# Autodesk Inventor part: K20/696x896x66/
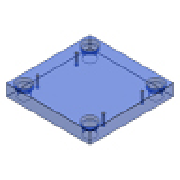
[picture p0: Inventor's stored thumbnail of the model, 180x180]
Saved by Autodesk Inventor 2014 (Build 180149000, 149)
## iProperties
IsCustomPart: 1
Created: 2009-11
Part Number: K20/696x896x66/
Material: DIN 1.1730
Description: Cavity Plate
Document SubType Name: Modeling
Designer: gaom
Standard Revision: 1
Manufacturer: HASCO
Language: en-US
Size Designation: 696x896x66/
Categories: <MemberInstance><Categories><Category DisplayName="Mold" InternalName="349578f2-f4d4-4954-8c09-8e99297a61c0" Mnemonic="MOLD"><Category DisplayName="Mold Plates"
Density: 7.82 g/cm^3
Appearance: Clear - Blue
Author: gaom
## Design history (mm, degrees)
sketch "Sketch1"
  geometry: L1 (-348, 448)-(348, 448); L2 (348, 448)-(348, -448); L3 (348, -448)-(-348, -448); L4 (-348, -448)-(-348, 448); 3 further points
  constraints: 8 end point, 2 midpoint, 2 parallel, 1 horizontal, 1 horizontal alignment, 1 perpendicular, 1 vertical alignment
  dimensions: "d126" = 696 distance between parallel lines of L2 L4 (= TW_); "d127" = 896 distance between parallel lines of L3 L1 (= TL)
extrude "Extrusion1" new body sketch "Sketch1" distance "d20" = 66 (= H_); taper "d30" = 0 deg
sketch "Sketch2"
  geometry: 6 further points
  dimensions: "d128" = 296 horizontal distance of point (0, 0) point (-296, 337) (= 0.5 x S1_W); "d129" = 337 vertical distance of point (0, 0) point (-296, 337) (= 0.5 x S1_L); "d130" = 396 vertical distance of point (0, 0) point (-296, 396) (= 0.5 x GP_L); "d131" = 296 horizontal distance of point (0, 0) point (-296, 396) (= 0.5 x GP_W); "d161" = 296 horizontal distance of point (0, 0) point (-296, -396) (= 0.5 x GP_W); "d162" = 396 vertical distance of point (0, 0) point (-296, -396) (= 0.5 x GP_L); "d163" = 296 horizontal distance of point (0, 0) point (296, 396) (= 0.5 x GP_W); "d164" = 396 vertical distance of point (0, 0) point (296, 396) (= 0.5 x GP_L); "d165" = 296 horizontal distance of point (296, -396) point (0, 0) (= 0.5 x GP_W); "d166" = 396 vertical distance of point (0, 0) point (296, -396) (= 0.5 x GP_L)
feature "Sculpt6"
sketch "Sketch3"
  geometry: 4 further points
hole "Hole14" sketch "Sketch3" at (142, 279.032), (-78, 279.032), (78, -279.032), (-142, -279.032) diameter "d188" = 3.4; stored, may be unused: countersink angle "d192" = 90 deg, drill point angle "d194" = 0 deg; dims "d189" = 6, "d190" = 4, "d191" = 2, "d193" = 8
sketch "Sketch4"
  geometry: 4 further points
hole "Hole15" sketch "Sketch4" at (154, 180.032), (-66, 180.032), (66, -180.032), (-154, -180.032) diameter "d195" = 3.4; stored, may be unused: countersink angle "d199" = 90 deg, drill point angle "d201" = 0 deg; dims "d196" = 6, "d197" = 4, "d198" = 2, "d200" = 8
sketch "Sketch5"
  geometry: 4 further points
hole "Hole16" sketch "Sketch5" at (78, 279.032), (-142, 279.032), (142, -279.032), (-78, -279.032) diameter "d202" = 3.4; stored, may be unused: countersink angle "d206" = 90 deg, drill point angle "d208" = 0 deg; dims "d203" = 6, "d204" = 4, "d205" = 2, "d207" = 8
sketch "Sketch6"
  geometry: 4 further points
hole "Hole17" sketch "Sketch6" at (66, 180.032), (-154, 180.032), (154, -180.032), (-66, -180.032) diameter "d209" = 3.4; stored, may be unused: countersink angle "d213" = 90 deg, drill point angle "d215" = 0 deg; dims "d210" = 6, "d211" = 4, "d212" = 2, "d214" = 8
sketch "Sketch7"
  geometry: 4 further points
hole "Hole18" sketch "Sketch7" at (154, 65.032), (-66, 65.032), (66, -65.032), (-154, -65.032) diameter "d216" = 3.4; stored, may be unused: countersink angle "d220" = 90 deg, drill point angle "d222" = 0 deg; dims "d217" = 6, "d218" = 4, "d219" = 2, "d221" = 8
sketch "Sketch8"
  geometry: 4 further points
hole "Hole19" sketch "Sketch8" at (66, 65.032), (-154, 65.032), (154, -65.032), (-66, -65.032) diameter "d223" = 3.4; stored, may be unused: countersink angle "d227" = 90 deg, drill point angle "d229" = 0 deg; dims "d224" = 6, "d225" = 4, "d226" = 2, "d228" = 8
workplane "Work Plane2"
workplane "Work Plane3"
workpoint "Work Point4"
workplane "Work Plane4"
workpoint "Work Point5"
workplane "Work Plane5"
workpoint "Work Point6"
workplane "Work Plane6"
workpoint "Work Point7"
workplane "Work Plane7"
workpoint "Work Point8"
workplane "Work Plane8"
workpoint "Work Point9"
workplane "Work Plane9"
workpoint "Work Point10"
workplane "Work Plane10"
workpoint "Work Point11"
feature "Sculpt99"
feature "Sculpt100"
feature "Sculpt101"
feature "Sculpt102"
feature "Sculpt103"
feature "Sculpt104"
feature "Sculpt105"
feature "Sculpt106"
feature "Sculpt107"
feature "Sculpt108"
feature "Sculpt109"
feature "Sculpt110"
feature "Sculpt111"
feature "Sculpt112"
feature "Sculpt113"
feature "Sculpt114"
feature "Sculpt115"
feature "Sculpt116"
feature "Sculpt117"
feature "Sculpt118"
sketch "Sketch9"
  geometry: L1 (-211.617, -350)-(211.617, -350); L2 (-220, 341.617)-(-220, -341.617); L3 (211.617, 350)-(-211.617, 350); L4 (220, -341.617)-(220, 341.617); A1 r 6 centre (216.464, -346.464) between (211.617, -350) and (220, -341.617); A2 r 6 centre (-216.464, -346.464) between (-220, -341.617) and (-211.617, -350); A3 r 6 centre (-216.464, 346.464) between (-211.617, 350) and (-220, 341.617); A4 r 6 centre (216.464, 346.464) between (220, 341.617) and (211.617, 350)
  constraints: 8 end point, 8 point on circle, 4 centre point
extrude "Extrusion2" cut sketch "Sketch9" distance "d231" = 120; taper "d232" = 0 deg
body "Solid1"
hole "Hole1" sketch "Sketch2" diameter "d132" = 54 (= GP_d1); stored, may be unused: countersink angle "d136" = 90 deg, drill point angle "d138" = 0 deg; dims "d133" = 6, "d134" = 61 (= GP_d2), "d135" = 10.3 (= GP_k), "d137" = 66 (= H_)
hole "Hole2" sketch "Sketch2" diameter "d139" = 17.294; stored, may be unused: countersink angle "d143" = 90 deg, drill point angle "d145" = 118 deg; dims "d140" = 32 (= S1_h1), "d141" = 61 (= GP_d2), "d142" = 10.3 (= GP_k), "d144" = 45 (= S1_h2)
pattern_linear "Rectangular Pattern2" dims "d154" = 674 (computed from S1_L, Ns), "d157" = 592 (computed from S1_W, Nw)
hole "Hole3" sketch "Sketch2" diameter "d167" = 54 (= GP_d1); stored, may be unused: countersink angle "d171" = 90 deg, drill point angle "d173" = 0 deg; dims "d168" = 6, "d169" = 61 (= GP_d2), "d170" = 10.3 (= GP_k), "d172" = 66 (= H_)
hole "Hole4" sketch "Sketch2" diameter "d174" = 54 (= GP_d1); stored, may be unused: countersink angle "d178" = 90 deg, drill point angle "d180" = 0 deg; dims "d175" = 6, "d176" = 61 (= GP_d2), "d177" = 10.3 (= GP_k), "d179" = 66 (= H_)
hole "Hole5" sketch "Sketch2" diameter "d181" = 54 (= GP_d1); stored, may be unused: countersink angle "d185" = 90 deg, drill point angle "d187" = 0 deg; dims "d182" = 6, "d183" = 61 (= GP_d2), "d184" = 10.3 (= GP_k), "d186" = 66 (= H_)
chamfer "Chamfer1" distance "d158" = 0.5; stored, may be unused: second distance "d159" = 2, angle "d160" = 45 deg
feature "Surface6"
body "Srf6"
feature "Surface99"
body "Srf99"
feature "Surface100"
body "Srf100"
feature "Surface101"
body "Srf101"
feature "Surface102"
body "Srf102"
feature "Surface103"
body "Srf103"
feature "Surface104"
body "Srf104"
feature "Surface105"
body "Srf105"
feature "Surface106"
body "Srf106"
feature "Surface107"
body "Srf107"
feature "Surface108"
body "Srf108"
feature "Surface109"
body "Srf109"
feature "Surface110"
body "Srf110"
feature "Surface111"
body "Srf111"
feature "Surface112"
body "Srf112"
feature "Surface113"
body "Srf113"
feature "Surface114"
body "Srf114"
feature "Surface115"
body "Srf115"
feature "Surface116"
body "Srf116"
feature "Surface117"
body "Srf117"
feature "Surface118"
body "Srf118"
other parameters: "TL" = 896 [user parameter; used in 1 equation term], "TW_" = 696 [user parameter; used in 1 equation term], "H_" = 66 [user parameter; used in 5 equation terms], "GP_W" = 592 [user parameter; used in 4 equation terms], "GP_d1" = 54 [user parameter; used in 4 equation terms], "GP_d2" = 61 [user parameter; used in 5 equation terms], "GP_k" = 10.3 [user parameter; used in 5 equation terms], "S1_L" = 674 [user parameter; used in 2 equation terms], "S1_W" = 592 [user parameter; used in 2 equation terms], "GP_L" = 792 [user parameter; used in 4 equation terms], "S1_h2" = 45 [user parameter; used in 1 equation term], "S1_h1" = 32 [user parameter; used in 1 equation term], "L" = 896 [user parameter], "W_" = 696 [user parameter], "d230" = 36.41956
